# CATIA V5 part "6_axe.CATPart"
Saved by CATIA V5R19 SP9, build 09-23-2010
Part number: 6_axe
Revision: ANY
Definition: UNKNOWN
Nomenclature: 6_axe
Source: Unknown
Bounding box of the stored display mesh (mm): x -50 to 50, y 40 to 360, z -50 to 50
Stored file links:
  Y:\fin de projet cabestan poupee\6_axe.CATPart
  Ass_arbre poupee_1.CATProduct
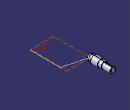
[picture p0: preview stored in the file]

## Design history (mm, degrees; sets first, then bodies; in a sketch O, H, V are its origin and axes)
TTRSSet1
f4a2d38f3ddc11d3a929006094b99c4b_11 "CATTPSSet"
Set1
  Sketch1 on face of Solid1, origin (0, 0, 0), H (1, 0, 0), V (0, 0, 1)
    circle A1 centre (0, 0) radius 33.4707
Body1 "NONE" (main body)
  Solid1: solid without history
  Pocket1: profile Sketch1, direction (0, 1, 0), up to face of Solid1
